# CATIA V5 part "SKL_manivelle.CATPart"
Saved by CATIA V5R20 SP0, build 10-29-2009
Part number: SKL_manivelle
Publications: "Plan_Ref", "Axe_A_manivelle", "A", "C", "Segment_AC", "Axe_C_manivelle", "Plan_Sec", "Plan_Ter"
Bounding box of the stored display mesh (mm): x -5 to 5, y 12 to 13.947, z 3.567 to 5.85
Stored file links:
  C:\Users\MATT\Desktop\CATIA_Projet_IAO\CATIA FINAL\SKL_manivelle.CATPart
  C:\Users\MATT\Desktop\CATIA_Projet_IAO\CATIA FINAL\SKL_Parametre_Projet_IAO.CATProduct
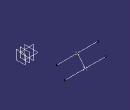
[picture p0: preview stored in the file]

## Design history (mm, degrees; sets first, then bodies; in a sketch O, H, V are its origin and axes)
External parameters (linked from other documents)
  External.AC = 3 mm
Set1
  Plane1 "Plan_Ref": type Offset, RefPlane Plane4, Offset 0
  Line1 "Axe_A_manivelle": type Normal, RefPoint Point1, RefSkin Plane1, Start -5, End 5
  Point1 "A": (0, 0, 0), relative to Point3
  Point2 "C": (0, 0, 0), relative to Point4
  Line2 "Segment_AC": type PtPt, FirstPoint Point1, SecondPoint Point2
  Line3 "Axe_C_manivelle": type Normal, RefPoint Point2, RefSkin Plane1, Start -5, End 5
  Plane2 "Plan_Sec": type Offset, RefPlane Plane5, Offset 0
  Plane3 "Plan_Ter": type Offset, RefPlane Plane6, Offset 0
Set2
  Plane4 "Plan_Ref": linked copy from another document
  Point3 "A": linked copy from another document
  Point4 "C": linked copy from another document
  Plane5 "Plan_Sec": linked copy from another document
  Plane6 "Plan_Ter": linked copy from another document
Body1 (main body)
